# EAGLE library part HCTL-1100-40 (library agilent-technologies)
General Purpose Motion Controller provides position and velocity control for DC, DC brushless and stepper motors. Source: http://www.avagotech.com/pc/downloadDocument.do?id=4609
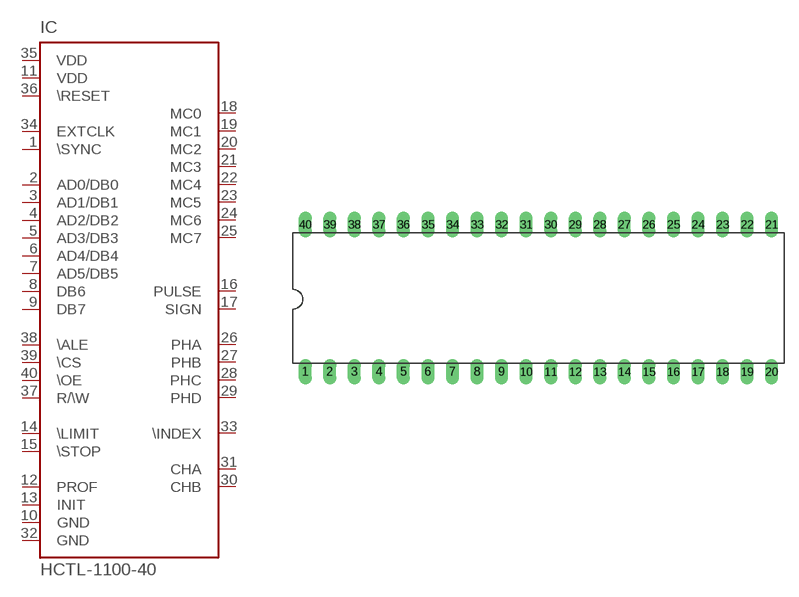
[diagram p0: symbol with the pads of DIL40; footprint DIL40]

Designator prefix IC

## HCTL-1100-40  [DIL40]
1  \SYNC  in
2  AD0/DB0
3  AD1/DB1
4  AD2/DB2
5  AD3/DB3
6  AD4/DB4
7  AD5/DB5
8  DB6
9  DB7
10  GND  pwr
11  VDD  pwr
12  PROF  out
13  INIT  out
14  \LIMIT  in
15  \STOP  in
16  PULSE  out
17  SIGN  out
18  MC0  out
19  MC1  out
20  MC2  out
21  MC3  out
22  MC4  out
23  MC5  out
24  MC6  out
25  MC7  out
26  PHA  out
27  PHB  out
28  PHC  out
29  PHD  out
30  CHB  in
31  CHA  in
32  GND  pwr
33  \INDEX  in
34  EXTCLK  in
35  VDD  pwr
36  \RESET  in
37  R/\W  in
38  \ALE  in
39  \CS  in
40  \OE  in

## Footprint DIL40 (pad centres in mm)
Dual In Line Package
drill 0.813 long: 1 -24.13,-7.62; 2 -21.59,-7.62; 3 -19.05,-7.62; 4 -16.51,-7.62; 5 -13.97,-7.62; 6 -11.43,-7.62; 7 -8.89,-7.62; 8 -6.35,-7.62; 9 -3.81,-7.62; 10 -1.27,-7.62; 11 1.27,-7.62; 12 3.81,-7.62; 13 6.35,-7.62; 14 8.89,-7.62; 15 11.43,-7.62; 16 13.97,-7.62; 17 16.51,-7.62; 18 19.05,-7.62; 19 21.59,-7.62; 20 24.13,-7.62; 21 24.13,7.62; 22 21.59,7.62; 23 19.05,7.62; 24 16.51,7.62; 25 13.97,7.62; 26 11.43,7.62; 27 8.89,7.62; 28 6.35,7.62; 29 3.81,7.62; 30 1.27,7.62; 31 -1.27,7.62; 32 -3.81,7.62; 33 -6.35,7.62; 34 -8.89,7.62; 35 -11.43,7.62; 36 -13.97,7.62; 37 -16.51,7.62; 38 -19.05,7.62; 39 -21.59,7.62; 40 -24.13,7.62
